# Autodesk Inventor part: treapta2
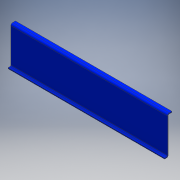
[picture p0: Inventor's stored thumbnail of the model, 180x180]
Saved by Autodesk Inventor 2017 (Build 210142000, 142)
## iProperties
Created: 2017-11
Part Number: treapta2
Material: Generic
Document SubType Name: Sheet Metal
Designer: iusti
Density: 1 g/cm^3
Sheet Metal Rule: Default_mm
Appearance: Default
Author: iusti
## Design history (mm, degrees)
node "Contour Flange1"
  sketch "Sketch1"
    geometry: L1 (20.807, 182.422)-(0.807, 182.422); L2 (0.807, 182.422)-(0.807, -17.578); L3 (0.807, -17.578)-(-19.193, -17.578); 1 further point
    constraints: 6 end point, 2 perpendicular, 1 horizontal
    dimensions: "d0" = 20 distance of L1.start L1.end; "d1" = 20 distance of L2.end L3.end; "d2" = 200 distance of L1.end L2.end
body "Solid1"
face "Plate1" dims "d3" = 5 (= BendReliefWidth), "d4" = 2.5 (= BendReliefDepth), "d5" = 10 (= MinimumRemnant), "d6" = 5 (= BendRadius), "d7" = 850, "d8" = 5 (= BendRadius), "d9" = 0.5, "d10" = 20 (= CornerReliefSize), "d11" = 5 (= GapSize), "d12" = 5 (= JacobiRadiusSize), "SeamGap" = 0.01, "Thickness" = 5 (derived)
bend "Bend1" dims "d3" = 5 (= BendReliefWidth), "d4" = 2.5 (= BendReliefDepth), "d5" = 10 (= MinimumRemnant), "d6" = 5 (= BendRadius), "d8" = 5 (= BendRadius), "d9" = 0.5, "SeamGap" = 0.01, "Thickness" = 5 (derived)
feature "Corner1" dims "d9" = 0.5, "d10" = 20 (= CornerReliefSize), "d11" = 5 (= GapSize), "d12" = 5 (= JacobiRadiusSize)
other parameters: "BendRadius" = 5 (= Thickness), "BendReliefWidth" = 5 (= Thickness), "BendReliefDepth" = 2.5 (= 0.5 x Thickness), "TransitionRadius" = 5 (= BendRadius), "JacobiRadiusSize" = 5 (= BendRadius), "GapSize" = 5 (= Thickness)
